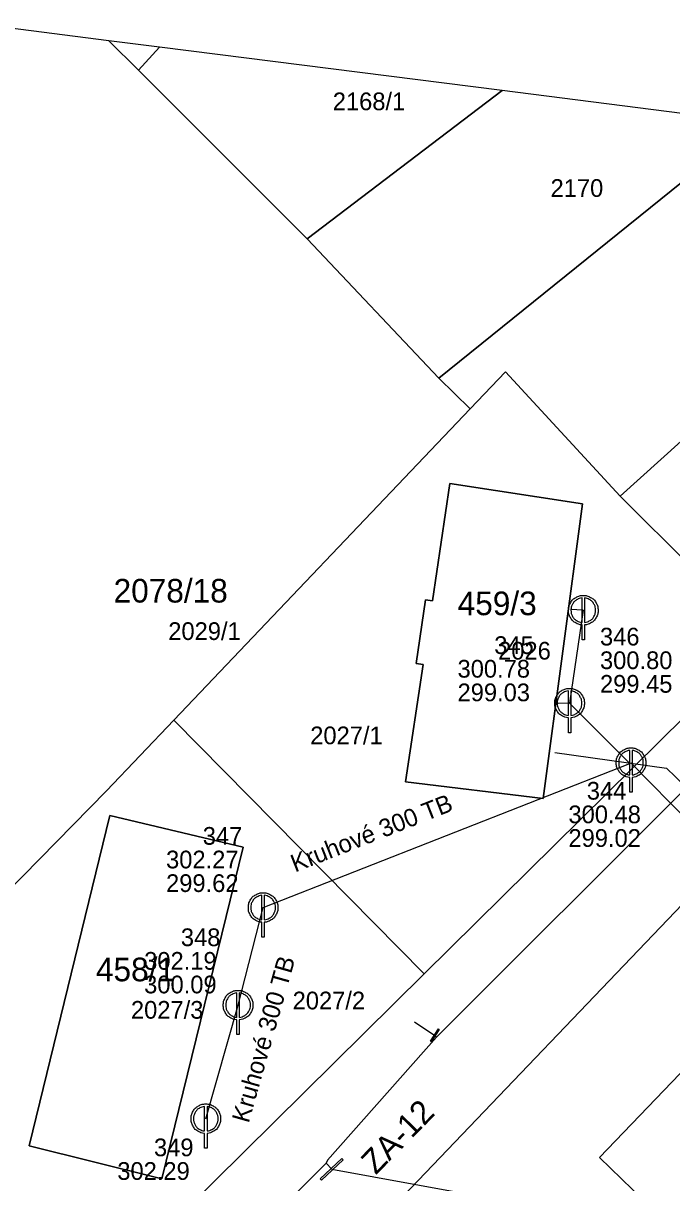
# Model space of a CAD drawing. Extents: x -570890 to -570546, y -1086481 to -1086296.
# Drawn here: x -570685 to -570630.1, y -1086405.7 to -1086307.5 of the extents above; entities that cross this region are included whole.
import ezdxf

# ---------------------------------------------------------------- set-up
doc = ezdxf.new("R2010")
doc.units = 0
for name, color, linetype in [('Adresní místo-text', 7, 'Continuous'), ('Armatura - popis', 7, 'Continuous'), ('Armatura vodovodní', 7, 'Continuous'), ('Default', 7, 'Continuous'), ('Kanalizační přípojka', 7, 'Continuous'), ('Kanalizační stoka', 7, 'Continuous'), ('Kanalizační šachta', 7, 'Continuous'), ('Parcela-polygon', 7, 'Continuous'), ('Parcela-text', 7, 'Continuous'), ('Popis kmenové stoky', 7, 'Continuous'), ('Popis šachty', 7, 'Continuous'), ('Vodovodní přípojka', 7, 'Continuous'), ('Vodovodní řad', 7, 'Continuous')]:
    doc.layers.add(name, color=color, linetype=linetype)

msp = doc.modelspace()

# ---------------------------------------------------------------- linework, layer by layer
at = {"layer": 'Armatura vodovodní'}
for points in [[(-570649.802, -1086392.721), (-570650.493, -1086393.763), (-570650.558, -1086393.719), (-570649.867, -1086392.677), (-570649.802, -1086392.721)], [(-570657.949, -1086403.764), (-570659.77, -1086405.478), (-570659.877, -1086405.364), (-570658.056, -1086403.651), (-570657.949, -1086403.764)]]:
    msp.add_lwpolyline(points, dxfattribs=at)
at = {"layer": 'Default'}
for points in [[(-570637.713, -1086358.468), (-570637.971, -1086358.45), (-570638.233, -1086358.304), (-570638.53, -1086358.14), (-570638.695, -1086357.843), (-570638.86, -1086357.545), (-570638.86, -1086357.22), (-570638.86, -1086356.893), (-570638.692, -1086356.593), (-570638.523, -1086356.292), (-570638.225, -1086356.131), (-570637.927, -1086355.97), (-570637.61, -1086355.97), (-570637.295, -1086355.97), (-570636.996, -1086356.131), (-570636.697, -1086356.292), (-570636.528, -1086356.593), (-570636.36, -1086356.893), (-570636.36, -1086357.22), (-570636.36, -1086357.545), (-570636.525, -1086357.843), (-570636.69, -1086358.14), (-570636.987, -1086358.304), (-570637.249, -1086358.45), (-570637.507, -1086358.468)], [(-570637.713, -1086356.182), (-570637.91, -1086356.199), (-570638.125, -1086356.314), (-570638.374, -1086356.449), (-570638.513, -1086356.699), (-570638.652, -1086356.949), (-570638.652, -1086357.22), (-570638.652, -1086357.491), (-570638.516, -1086357.738), (-570638.379, -1086357.984), (-570638.13, -1086358.121), (-570637.918, -1086358.241), (-570637.713, -1086358.255)], [(-570637.507, -1086358.255), (-570637.302, -1086358.241), (-570637.088, -1086358.121), (-570636.841, -1086357.984), (-570636.704, -1086357.738), (-570636.568, -1086357.491), (-570636.568, -1086357.22), (-570636.568, -1086356.949), (-570636.708, -1086356.699), (-570636.848, -1086356.449), (-570637.097, -1086356.314), (-570637.31, -1086356.199), (-570637.507, -1086356.182)], [(-570638.873, -1086366.338), (-570639.131, -1086366.32), (-570639.393, -1086366.174), (-570639.69, -1086366.01), (-570639.855, -1086365.713), (-570640.02, -1086365.415), (-570640.02, -1086365.09), (-570640.02, -1086364.763), (-570639.852, -1086364.463), (-570639.683, -1086364.162), (-570639.385, -1086364.001), (-570639.087, -1086363.84), (-570638.77, -1086363.84), (-570638.455, -1086363.84), (-570638.156, -1086364.001), (-570637.857, -1086364.162), (-570637.688, -1086364.463), (-570637.52, -1086364.763), (-570637.52, -1086365.09), (-570637.52, -1086365.415), (-570637.685, -1086365.713), (-570637.85, -1086366.01), (-570638.147, -1086366.174), (-570638.409, -1086366.32), (-570638.667, -1086366.338)], [(-570638.873, -1086364.052), (-570639.07, -1086364.069), (-570639.285, -1086364.184), (-570639.534, -1086364.319), (-570639.673, -1086364.569), (-570639.812, -1086364.819), (-570639.812, -1086365.09), (-570639.812, -1086365.361), (-570639.676, -1086365.608), (-570639.539, -1086365.854), (-570639.29, -1086365.991), (-570639.078, -1086366.111), (-570638.873, -1086366.125)], [(-570638.667, -1086366.125), (-570638.462, -1086366.111), (-570638.248, -1086365.991), (-570638.001, -1086365.854), (-570637.864, -1086365.608), (-570637.728, -1086365.361), (-570637.728, -1086365.09), (-570637.728, -1086364.819), (-570637.868, -1086364.569), (-570638.008, -1086364.319), (-570638.257, -1086364.184), (-570638.47, -1086364.069), (-570638.667, -1086364.052)], [(-570633.673, -1086371.378), (-570633.931, -1086371.36), (-570634.193, -1086371.214), (-570634.49, -1086371.05), (-570634.655, -1086370.753), (-570634.82, -1086370.455), (-570634.82, -1086370.13), (-570634.82, -1086369.803), (-570634.652, -1086369.503), (-570634.483, -1086369.202), (-570634.185, -1086369.041), (-570633.887, -1086368.88), (-570633.57, -1086368.88), (-570633.255, -1086368.88), (-570632.956, -1086369.041), (-570632.657, -1086369.202), (-570632.488, -1086369.503), (-570632.32, -1086369.803), (-570632.32, -1086370.13), (-570632.32, -1086370.455), (-570632.485, -1086370.753), (-570632.65, -1086371.05), (-570632.947, -1086371.214), (-570633.209, -1086371.36), (-570633.467, -1086371.378)], [(-570633.673, -1086369.092), (-570633.87, -1086369.109), (-570634.085, -1086369.224), (-570634.334, -1086369.359), (-570634.473, -1086369.609), (-570634.612, -1086369.859), (-570634.612, -1086370.13), (-570634.612, -1086370.401), (-570634.476, -1086370.648), (-570634.339, -1086370.894), (-570634.09, -1086371.031), (-570633.878, -1086371.151), (-570633.673, -1086371.165)], [(-570633.467, -1086371.165), (-570633.262, -1086371.151), (-570633.048, -1086371.031), (-570632.801, -1086370.894), (-570632.664, -1086370.648), (-570632.528, -1086370.401), (-570632.528, -1086370.13), (-570632.528, -1086369.859), (-570632.668, -1086369.609), (-570632.808, -1086369.359), (-570633.057, -1086369.224), (-570633.27, -1086369.109), (-570633.467, -1086369.092)], [(-570664.823, -1086383.648), (-570665.081, -1086383.63), (-570665.343, -1086383.484), (-570665.64, -1086383.32), (-570665.805, -1086383.023), (-570665.97, -1086382.725), (-570665.97, -1086382.4), (-570665.97, -1086382.073), (-570665.802, -1086381.773), (-570665.633, -1086381.472), (-570665.335, -1086381.311), (-570665.037, -1086381.15), (-570664.72, -1086381.15), (-570664.405, -1086381.15), (-570664.106, -1086381.311), (-570663.807, -1086381.472), (-570663.638, -1086381.773), (-570663.47, -1086382.073), (-570663.47, -1086382.4), (-570663.47, -1086382.725), (-570663.635, -1086383.023), (-570663.8, -1086383.32), (-570664.097, -1086383.484), (-570664.359, -1086383.63), (-570664.617, -1086383.648)], [(-570664.823, -1086381.362), (-570665.02, -1086381.379), (-570665.235, -1086381.494), (-570665.484, -1086381.629), (-570665.623, -1086381.879), (-570665.762, -1086382.129), (-570665.762, -1086382.4), (-570665.762, -1086382.671), (-570665.626, -1086382.918), (-570665.489, -1086383.164), (-570665.24, -1086383.301), (-570665.028, -1086383.421), (-570664.823, -1086383.435)], [(-570664.617, -1086383.435), (-570664.412, -1086383.421), (-570664.198, -1086383.301), (-570663.951, -1086383.164), (-570663.814, -1086382.918), (-570663.678, -1086382.671), (-570663.678, -1086382.4), (-570663.678, -1086382.129), (-570663.818, -1086381.879), (-570663.958, -1086381.629), (-570664.207, -1086381.494), (-570664.42, -1086381.379), (-570664.617, -1086381.362)], [(-570666.943, -1086391.908), (-570667.201, -1086391.89), (-570667.463, -1086391.744), (-570667.76, -1086391.58), (-570667.925, -1086391.283), (-570668.09, -1086390.985), (-570668.09, -1086390.66), (-570668.09, -1086390.333), (-570667.922, -1086390.033), (-570667.753, -1086389.732), (-570667.455, -1086389.571), (-570667.157, -1086389.41), (-570666.84, -1086389.41), (-570666.525, -1086389.41), (-570666.226, -1086389.571), (-570665.927, -1086389.732), (-570665.758, -1086390.033), (-570665.59, -1086390.333), (-570665.59, -1086390.66), (-570665.59, -1086390.985), (-570665.755, -1086391.283), (-570665.92, -1086391.58), (-570666.217, -1086391.744), (-570666.479, -1086391.89), (-570666.737, -1086391.908)], [(-570666.943, -1086389.622), (-570667.14, -1086389.639), (-570667.355, -1086389.754), (-570667.604, -1086389.889), (-570667.743, -1086390.139), (-570667.882, -1086390.389), (-570667.882, -1086390.66), (-570667.882, -1086390.931), (-570667.746, -1086391.178), (-570667.609, -1086391.424), (-570667.36, -1086391.561), (-570667.148, -1086391.681), (-570666.943, -1086391.695)], [(-570666.737, -1086391.695), (-570666.532, -1086391.681), (-570666.318, -1086391.561), (-570666.071, -1086391.424), (-570665.934, -1086391.178), (-570665.798, -1086390.931), (-570665.798, -1086390.66), (-570665.798, -1086390.389), (-570665.938, -1086390.139), (-570666.078, -1086389.889), (-570666.327, -1086389.754), (-570666.54, -1086389.639), (-570666.737, -1086389.622)], [(-570669.673, -1086401.528), (-570669.931, -1086401.51), (-570670.193, -1086401.364), (-570670.49, -1086401.2), (-570670.655, -1086400.903), (-570670.82, -1086400.605), (-570670.82, -1086400.28), (-570670.82, -1086399.953), (-570670.652, -1086399.653), (-570670.483, -1086399.352), (-570670.185, -1086399.191), (-570669.887, -1086399.03), (-570669.57, -1086399.03), (-570669.255, -1086399.03), (-570668.956, -1086399.191), (-570668.657, -1086399.352), (-570668.488, -1086399.653), (-570668.32, -1086399.953), (-570668.32, -1086400.28), (-570668.32, -1086400.605), (-570668.485, -1086400.903), (-570668.65, -1086401.2), (-570668.947, -1086401.364), (-570669.209, -1086401.51), (-570669.467, -1086401.528)], [(-570669.673, -1086399.242), (-570669.87, -1086399.259), (-570670.085, -1086399.374), (-570670.334, -1086399.509), (-570670.473, -1086399.759), (-570670.612, -1086400.009), (-570670.612, -1086400.28), (-570670.612, -1086400.551), (-570670.476, -1086400.798), (-570670.339, -1086401.044), (-570670.09, -1086401.181), (-570669.878, -1086401.301), (-570669.673, -1086401.315)], [(-570669.467, -1086401.315), (-570669.262, -1086401.301), (-570669.048, -1086401.181), (-570668.801, -1086401.044), (-570668.664, -1086400.798), (-570668.528, -1086400.551), (-570668.528, -1086400.28), (-570668.528, -1086400.009), (-570668.668, -1086399.759), (-570668.808, -1086399.509), (-570669.057, -1086399.374), (-570669.27, -1086399.259), (-570669.467, -1086399.242)]]:
    msp.add_open_spline(points, degree=3, dxfattribs=at)
at = {"layer": 'Kanalizační přípojka'}
for p, q in [((-570637.61, -1086357.22), (-570638.77, -1086365.09)), ((-570638.77, -1086365.09), (-570633.68, -1086370.21))]:
    msp.add_line(p, q, dxfattribs=at)
for points in [[(-570637.61, -1086357.22), (-570638.679, -1086357.148)], [(-570638.77, -1086365.09), (-570639.724, -1086365.13)]]:
    msp.add_lwpolyline(points, dxfattribs=at)
at = {"layer": 'Kanalizační stoka'}
for p, q in [((-570664.72, -1086382.4), (-570633.68, -1086370.21)), ((-570666.84, -1086390.66), (-570664.72, -1086382.4)), ((-570669.57, -1086400.28), (-570666.84, -1086390.66))]:
    msp.add_line(p, q, dxfattribs=at)
msp.add_lwpolyline([(-570633.57, -1086370.13), (-570628.54, -1086375.29)], dxfattribs=at)
at = {"layer": 'Kanalizační šachta'}
for points in [[(-570637.713, -1086358.255), (-570637.713, -1086356.182)], [(-570637.507, -1086356.182), (-570637.507, -1086358.255)], [(-570637.507, -1086358.468), (-570637.507, -1086359.72), (-570637.713, -1086359.72), (-570637.713, -1086358.468)], [(-570638.873, -1086366.125), (-570638.873, -1086364.052)], [(-570638.667, -1086364.052), (-570638.667, -1086366.125)], [(-570638.667, -1086366.338), (-570638.667, -1086367.59), (-570638.873, -1086367.59), (-570638.873, -1086366.338)], [(-570633.673, -1086371.165), (-570633.673, -1086369.092)], [(-570633.467, -1086369.092), (-570633.467, -1086371.165)], [(-570633.467, -1086371.378), (-570633.467, -1086372.63), (-570633.673, -1086372.63), (-570633.673, -1086371.378)], [(-570664.823, -1086383.435), (-570664.823, -1086381.362)], [(-570664.617, -1086381.362), (-570664.617, -1086383.435)], [(-570664.617, -1086383.648), (-570664.617, -1086384.9), (-570664.823, -1086384.9), (-570664.823, -1086383.648)], [(-570666.943, -1086391.695), (-570666.943, -1086389.622)], [(-570666.737, -1086389.622), (-570666.737, -1086391.695)], [(-570666.737, -1086391.908), (-570666.737, -1086393.16), (-570666.943, -1086393.16), (-570666.943, -1086391.908)], [(-570669.673, -1086401.315), (-570669.673, -1086399.242)], [(-570669.467, -1086399.242), (-570669.467, -1086401.315)], [(-570669.467, -1086401.528), (-570669.467, -1086402.78), (-570669.673, -1086402.78), (-570669.673, -1086401.528)]]:
    msp.add_lwpolyline(points, dxfattribs=at)
at = {"layer": 'Parcela-polygon'}
for p, q in [((-570677.774, -1086308.994), (-570689.451, -1086307.511)), ((-570673.497, -1086309.536), (-570677.774, -1086308.994)), ((-570644.466, -1086313.222), (-570673.497, -1086309.536)), ((-570623.019, -1086315.944), (-570644.466, -1086313.222))]:
    msp.add_line(p, q, dxfattribs=at)
for points in [[(-570689.451, -1086307.511), (-570695.97, -1086315.11), (-570710.14, -1086332.11), (-570702.61, -1086339.28), (-570695.76, -1086345.69), (-570702.6, -1086353.01), (-570701.76, -1086353.8), (-570696.83, -1086358.62), (-570712.07, -1086377.35), (-570714.03, -1086378.44), (-570705.67, -1086387.65), (-570701.98, -1086391.22), (-570699.23, -1086394.15), (-570677.97, -1086372.52), (-570672.28, -1086366.53), (-570647.18, -1086340.16), (-570649.83, -1086337.57), (-570661, -1086325.77), (-570675.27, -1086311.5), (-570677.774, -1086308.994)], [(-570677.774, -1086308.994), (-570675.27, -1086311.5), (-570673.497, -1086309.536)], [(-570673.497, -1086309.536), (-570675.27, -1086311.5), (-570661, -1086325.77), (-570644.466, -1086313.222)], [(-570644.466, -1086313.222), (-570661, -1086325.77), (-570649.83, -1086337.57), (-570623.019, -1086315.944)], [(-570623.019, -1086315.944), (-570649.83, -1086337.57), (-570647.18, -1086340.16), (-570644.19, -1086337.02), (-570634.5, -1086347.55), (-570612.11, -1086327.37), (-570606.63, -1086322.44), (-570602.293, -1086318.575)], [(-570583.234, -1086320.674), (-570596.46, -1086333.85), (-570601.07, -1086338.45), (-570622.35, -1086359.65), (-570651.08, -1086388.01), (-570679.02, -1086415.64), (-570677.75, -1086417.52), (-570669.23, -1086426.82), (-570669.33, -1086425.11), (-570668.65, -1086423.5), (-570653.44, -1086407.45), (-570627.97, -1086380.81), (-570613.03, -1086365.73), (-570583.9, -1086336.34), (-570582.04, -1086334.46), (-570579.74, -1086332.2), (-570577.95, -1086330.46), (-570571.036, -1086323.783)], [(-570615.756, -1086423.443), (-570636.25, -1086403.55), (-570626.03, -1086392.93), (-570616.53, -1086402.15), (-570611.49, -1086396.95), (-570619.89, -1086389.23), (-570627.97, -1086380.81), (-570653.44, -1086407.45), (-570629.616, -1086433.71)], [(-570602.525, -1086413.642), (-570603.3, -1086412.89), (-570600.46, -1086409.96), (-570603.93, -1086406.83), (-570606.02, -1086408.98), (-570606.88, -1086408.15), (-570603.52, -1086404.68), (-570611.49, -1086396.95), (-570616.53, -1086402.15), (-570626.03, -1086392.93), (-570636.25, -1086403.55), (-570615.756, -1086423.443)]]:
    msp.add_lwpolyline(points, dxfattribs=at)
for points in [[(-570634.5, -1086347.55), (-570622.35, -1086359.65), (-570601.07, -1086338.45), (-570612.11, -1086327.37)], [(-570672.28, -1086366.53), (-570651.08, -1086388.01), (-570622.35, -1086359.65), (-570634.5, -1086347.55), (-570644.19, -1086337.02), (-570647.18, -1086340.16)], [(-570652.66, -1086371.76), (-570641.02, -1086373.17), (-570637.68, -1086348.2), (-570648.9, -1086346.5), (-570650.38, -1086356.42), (-570650.97, -1086356.33), (-570651.77, -1086361.73), (-570651.18, -1086361.82)], [(-570637.68, -1086348.2), (-570641.02, -1086373.17), (-570652.66, -1086371.76), (-570651.18, -1086361.82), (-570651.77, -1086361.73), (-570650.97, -1086356.33), (-570650.38, -1086356.42), (-570648.9, -1086346.5)], [(-570651.08, -1086388.01), (-570672.28, -1086366.53), (-570677.97, -1086372.52), (-570699.23, -1086394.15), (-570679.02, -1086415.64)], [(-570673.29, -1086405.38), (-570684.54, -1086402.57), (-570677.7, -1086374.6), (-570666.41, -1086377.27)], [(-570666.41, -1086377.27), (-570677.7, -1086374.6), (-570684.54, -1086402.57), (-570673.29, -1086405.38)]]:
    msp.add_lwpolyline(points, close=True, dxfattribs=at)
at = {"layer": 'Vodovodní přípojka'}
for points in [[(-570640.028, -1086369.256), (-570630.57, -1086370.6), (-570629.8, -1086371.34), (-570629.03, -1086372.08), (-570628.88, -1086372.24)], [(-570651.9, -1086392.08), (-570650.18, -1086393.22), (-570650.03, -1086393.37)]]:
    msp.add_lwpolyline(points, dxfattribs=at)
at = {"layer": 'Vodovodní řad'}
for points in [[(-570589.03, -1086332.646), (-570591.4, -1086334.95), (-570610.78, -1086354.1), (-570628.88, -1086372.24), (-570650.03, -1086393.37), (-570659.266, -1086403.778), (-570659.385, -1086404.052)], [(-570659.385, -1086404.052), (-570670.501, -1086415.209)], [(-570659.385, -1086404.052), (-570658.913, -1086404.564)], [(-570658.913, -1086404.564), (-570640.507, -1086407.898), (-570635.226, -1086412.605), (-570621.47, -1086424.864), (-570619.347, -1086426.103)]]:
    msp.add_lwpolyline(points, dxfattribs=at)

# ---------------------------------------------------------------- texts
at = {"layer": 'Adresní místo-text'}
for s, p in [('2078/18', (-570677.378, -1086356.57)), ('459/3', (-570648.245, -1086357.64)), ('458/1', (-570678.875, -1086388.64))]:
    msp.add_text(s, height=2, dxfattribs=at).set_placement(p)
at = {"layer": 'Armatura - popis'}
msp.add_text('ZA-12', height=2, rotation=45.45102, dxfattribs=at).set_placement((-570655.181, -1086405.078))
at = {"layer": 'Parcela-text'}
for s, p in [('2168/1', (-570658.82, -1086314.88)), ('2170', (-570640.38, -1086322.22)), ('2029/1', (-570672.75, -1086359.74)), ('2026', (-570644.82, -1086361.4)), ('2027/1', (-570660.73, -1086368.57)), ('2027/2', (-570662.22, -1086391.02)), ('2027/3', (-570675.91, -1086391.81))]:
    msp.add_text(s, height=1.5, dxfattribs=at).set_placement(p)
at = {"layer": 'Popis kmenové stoky'}
for rotation, p in [(21.44088, (-570662.016, -1086379.436)), (74.1569, (-570665.946, -1086400.712))]:
    msp.add_text('Kruhové 300 TB', height=1.5, rotation=rotation, dxfattribs=at).set_placement(p)
at = {"layer": 'Popis šachty'}
for s, p in [('346', (-570636.195, -1086360.206)), ('345', (-570645.149, -1086360.927)), ('300.78', (-570648.256, -1086362.927)), ('300.80', (-570636.195, -1086362.206)), ('299.03', (-570648.256, -1086364.927)), ('299.45', (-570636.195, -1086364.206)), ('344', (-570637.311, -1086373.258)), ('300.48', (-570638.865, -1086375.258)), ('347', (-570669.829, -1086377.08)), ('299.02', (-570638.865, -1086377.258)), ('302.27', (-570672.936, -1086379.08)), ('299.62', (-570672.936, -1086381.08)), ('348', (-570671.684, -1086385.663)), ('302.19', (-570674.791, -1086387.663)), ('300.09', (-570674.791, -1086389.663)), ('349', (-570673.959, -1086403.456)), ('302.29', (-570677.066, -1086405.456))]:
    msp.add_text(s, height=1.5, dxfattribs=at).set_placement(p)

doc.saveas('drawing.dxf')
